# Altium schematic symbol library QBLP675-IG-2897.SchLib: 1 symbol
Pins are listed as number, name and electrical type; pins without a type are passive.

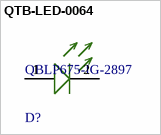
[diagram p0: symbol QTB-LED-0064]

## QTB-LED-0064
designator D?, comment QBLP675-IG-2897
LED GREEN CLEAR 2PLCC SMD; Manufacturer: QT Brightek (QTB); Luminous Intensity: 1120mcd; Test Current: 20mA; Lens Color: Colorless; Lens Style: Oval with Flat Top; Forward Voltage: 3.2V; Wavelength - Dominant: 524nm; Viewing Angle: 120°
footprint QBLP675-IG-2897-MFG
pins: 1 ANODE (+), 2 CATHODE (-)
